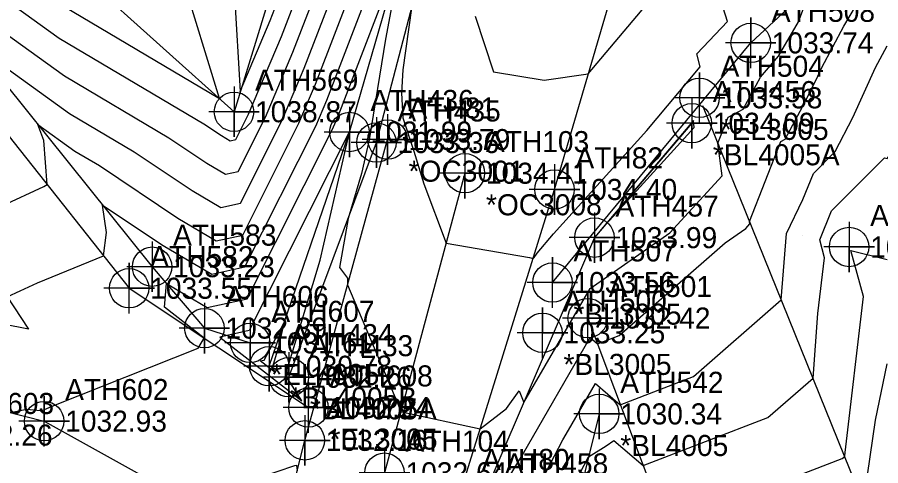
# Model space of a CAD drawing. Extents: x 1213164 to 1213550, y 766120 to 766870.
# Drawn here: x 1213316.7 to 1213419.3, y 766602.7 to 766656 of the extents above; entities that cross this region are included whole.
import ezdxf

# ---------------------------------------------------------------- set-up
doc = ezdxf.new("R2010")
doc.units = 0
for name, color, linetype in [('Default', 7, 'Continuous'), ('Exist DTM Breakline', 7, 'Continuous'), ('Exist DTM Breakline Cogo Comment', 7, 'Continuous'), ('Exist DTM Breakline Cogo Elevation', 7, 'Continuous'), ('Exist DTM Breakline Cogo Number', 7, 'Continuous'), ('Exist DTM Breakline Cogo Point CELL', 7, 'Continuous'), ('Exist DTM Crownline', 7, 'Continuous'), ('Exist DTM Crownline Cogo Comment', 7, 'Continuous'), ('Exist DTM Crownline Cogo Elevation', 7, 'Continuous'), ('Exist DTM Crownline Cogo Number', 7, 'Continuous'), ('Exist DTM Crownline Cogo Point CELL', 7, 'Continuous'), ('Exist DTM QL2 LIDAR Elevation Point', 7, 'Continuous'), ('Exist DTM Regular Point CELL', 7, 'Continuous'), ('Exist DTM Regular Point Cogo Elevation', 7, 'Continuous'), ('Exist DTM Regular Point Cogo Number', 7, 'Continuous'), ('Exist Roads EOP', 7, 'Continuous'), ('Exist Roads EOP Cogo Comment', 7, 'Continuous'), ('Exist Roads EOP Cogo Elevation', 7, 'Continuous'), ('Exist Roads EOP Cogo Number', 7, 'Continuous'), ('Exist Roads EOP Cogo Point CELL', 7, 'Continuous'), ('Exist Roads Soil', 7, 'Continuous'), ('Exist Roads Soil Cogo Comment', 7, 'Continuous'), ('Exist Roads Soil Cogo Elevation', 7, 'Continuous'), ('Exist Roads Soil Cogo Number', 7, 'Continuous'), ('Exist Roads Soil Cogo Point CELL', 7, 'Continuous')]:
    doc.layers.add(name, color=color, linetype=linetype)

msp = doc.modelspace()

# ---------------------------------------------------------------- linework, layer by layer
at = {"layer": 'Default'}
for points in [[(1213229.91, 766628.63), (1213231.61, 766625.47), (1213233.56, 766624.18), (1213260.61, 766623.01), (1213260.95, 766623.11), (1213261.75, 766623.57), (1213263.33, 766624), (1213274.44, 766627.3), (1213277.6, 766627.87), (1213300.48, 766625.1), (1213305.42, 766624.33), (1213315.52, 766622.75), (1213319.13, 766624.42), (1213326.96, 766627.62), (1213327.29, 766630.38), (1213326.85, 766633.66), (1213334.04, 766628.84), (1213339.8, 766625.45), (1213343.74, 766626.32), (1213352.15, 766643.03), (1213353.46, 766646.12), (1213362.47, 766669.52)], [(1213230, 766635.98), (1213235.84, 766637.33), (1213260.48, 766636.44), (1213263.49, 766635.93), (1213267.36, 766635.23), (1213272.93, 766634.4), (1213278.24, 766635.46), (1213299.19, 766632.93), (1213309.93, 766631.26), (1213319.85, 766635.85), (1213320.25, 766636.1), (1213319.86, 766641.32), (1213319.16, 766643.22), (1213323.53, 766640.07), (1213326.46, 766638.34), (1213335.77, 766632.11), (1213340.35, 766629.41), (1213343.48, 766630.1), (1213350.16, 766643.38), (1213352.12, 766648.01), (1213359.49, 766667.16)], [(1213229.91, 766642.9), (1213230, 766644.71), (1213234.36, 766644.36), (1213238.15, 766644.35), (1213243, 766643.74), (1213255.18, 766643.3), (1213261.95, 766642.16), (1213270.65, 766640.58), (1213274.2, 766640.05), (1213285.35, 766642.28), (1213297.9, 766640.76), (1213304.33, 766639.76), (1213310.28, 766642.51), (1213313.54, 766644.58), (1213313.3, 766647.81), (1213311.48, 766652.77), (1213322.92, 766644.54), (1213330.59, 766639.99), (1213337.5, 766635.37), (1213340.89, 766633.37), (1213343.21, 766633.88), (1213348.17, 766643.73), (1213350.78, 766649.9), (1213356.51, 766664.8)], [(1213363.53, 766657.03), (1213362.49, 766649.7), (1213362.33, 766646.97), (1213362.51, 766644.01), (1213363.81, 766640.07), (1213364.99, 766636.19), (1213367.65, 766629.14), (1213377.54, 766627.42), (1213377.97, 766627.33), (1213378.11, 766627.45), (1213378.47, 766627.94), (1213380.39, 766630.24), (1213391.47, 766642.51), (1213397.82, 766650.08), (1213397.41, 766651.62), (1213401.07, 766655.44), (1213398.13, 766664.72)], [(1213315.9, 766609.02), (1213317.84, 766609.42), (1213319.43, 766609.25), (1213319.68, 766609.27), (1213321.07, 766609.84), (1213338.2, 766616.67), (1213338.92, 766617.85), (1213334.2, 766621.55), (1213334.44, 766624.33), (1213339.26, 766621.48), (1213344.01, 766622.53), (1213354.14, 766642.68), (1213354.8, 766644.23), (1213362.46, 766664.13), (1213360.44, 766653.35), (1213358.52, 766641.4), (1213357.61, 766637.42), (1213356, 766632.06), (1213354.96, 766626.26), (1213355.91, 766624.99), (1213355.93, 766624.2), (1213361.9, 766610.07), (1213362.26, 766609.11), (1213362.55, 766609.06), (1213371.7, 766607.1), (1213374.8, 766609.52), (1213376.32, 766611.61), (1213376.87, 766610.22), (1213384.74, 766623.74), (1213394.22, 766630.34), (1213400.41, 766637.14), (1213399.92, 766641.02), (1213401.12, 766644.08), (1213402.93, 766645.05), (1213404.96, 766648.84), (1213407.13, 766651.35), (1213409.49, 766655.4), (1213411.03, 766659.6)], [(1213305.9, 766660.82), (1213322.31, 766649.01), (1213334.72, 766641.65), (1213339.22, 766638.63), (1213341.44, 766637.33), (1213342.95, 766637.66), (1213346.18, 766644.08), (1213349.44, 766651.8), (1213353.54, 766662.44)], [(1213309.95, 766661.94), (1213321.7, 766653.48), (1213338.85, 766643.3), (1213340.95, 766641.9), (1213341.98, 766641.29), (1213342.68, 766641.45), (1213344.19, 766644.44), (1213348.1, 766653.69), (1213350.56, 766660.08)], [(1213321.09, 766657.94), (1213340.71, 766646.3), (1213336.25, 766660.9)], [(1213342.51, 766658.57), (1213343.19, 766647.14), (1213346.76, 766655.58), (1213347.59, 766657.72)], [(1213371.08, 766656.07), (1213373.25, 766649.48), (1213379.3, 766648.5), (1213384.51, 766649.22), (1213392.44, 766658.66)], [(1213374.99, 766601.19), (1213376.71, 766603.99), (1213384.73, 766617.93), (1213385.6, 766617.18), (1213388.19, 766618.18), (1213400.76, 766629.17), (1213403.24, 766630.89), (1213403.72, 766631.42), (1213403.68, 766631.72), (1213407.39, 766641.2), (1213407.92, 766641.48), (1213410, 766645.38), (1213411.56, 766648.44), (1213412.27, 766650), (1213414.88, 766654.88), (1213417.13, 766658.74)], [(1213353.03, 766538.71), (1213360.06, 766554.63), (1213361.94, 766557.96), (1213368.09, 766570.88), (1213369.21, 766573.11), (1213376.08, 766587.44), (1213384.56, 766603.77), (1213386.66, 766605.05), (1213387.56, 766605.71), (1213391.04, 766602.72), (1213405.84, 766608.43), (1213411.21, 766613.12), (1213411.8, 766620.77), (1213412.59, 766627.41), (1213412.01, 766629.52), (1213413.41, 766632.98), (1213419.7, 766639.25), (1213420, 766639.17), (1213420.37, 766639.63), (1213420.63, 766640), (1213424.33, 766645.67), (1213426.37, 766650), (1213427.85, 766652.15), (1213430, 766656.29)], [(1213374.46, 766592.25), (1213381.5, 766605.8), (1213382.19, 766606.92), (1213385.38, 766612.47), (1213388.32, 766609.95), (1213397.02, 766613.3), (1213407.44, 766622.42), (1213408.05, 766630.3), (1213410, 766634.3), (1213411.26, 766637.41), (1213413.86, 766640), (1213415.93, 766644.07), (1213418.63, 766650), (1213420, 766652.57)], [(1213397.1, 766642.87), (1213397, 766643.68), (1213385.86, 766630.52), (1213397.1, 766642.87)], [(1213350.52, 766610.43), (1213348.56, 766613.44), (1213352.67, 766627.12), (1213356.16, 766642.32), (1213356.18, 766642.4), (1213356.19, 766642.48), (1213356.14, 766642.34), (1213356.13, 766642.33), (1213344.27, 766618.75), (1213341.64, 766618.17), (1213340.77, 766617.96), (1213350.52, 766610.43)], [(1213353.14, 766525.66), (1213361.52, 766549.65), (1213362.63, 766551.86), (1213367.85, 766562.26), (1213372.47, 766571.97), (1213375.15, 766577.31), (1213377.7, 766582.63), (1213380.85, 766588.68), (1213389.17, 766593.76), (1213392.72, 766596.38), (1213393.76, 766595.49), (1213414.67, 766603.56), (1213414.97, 766603.82), (1213415.01, 766604.26), (1213417.21, 766622.79), (1213415.71, 766628.28), (1213420, 766627.19)], [(1213346.03, 766615.26), (1213348.37, 766619.62), (1213347.73, 766616.82), (1213346.98, 766614.32), (1213347.34, 766613.78), (1213345.56, 766615.15), (1213346.03, 766615.26)], [(1213356.49, 766527.5), (1213362.2, 766543.86), (1213364.74, 766548.91), (1213376.71, 766572.75), (1213376.86, 766573.06), (1213377.13, 766573.6), (1213382.4, 766576.55), (1213385.24, 766579.91), (1213390, 766583.08), (1213391.68, 766584.23), (1213396.48, 766588.25), (1213409.54, 766593.3), (1213418.74, 766594.53), (1213417.67, 766601.59), (1213418.64, 766608.1), (1213420, 766614.82)], [(1213337.1, 766598.45), (1213349.69, 766602.72), (1213349.86, 766602.78), (1213349.95, 766602.12)]]:
    msp.add_lwpolyline(points, dxfattribs=at)
at = {"layer": 'Exist DTM Breakline'}
for points in [[(1213393.73, 766837.71), (1213387.94, 766804.2), (1213372.97, 766750.1), (1213364.41, 766714.77), (1213354.91, 766685.16), (1213342.45, 766644.74), (1213315.98, 766668.51), (1213286.51, 766700.01), (1213270.13, 766717.65)], [(1213346.63, 766614.52), (1213356.15, 766642.33), (1213365.89, 766675.98), (1213376.51, 766712.04), (1213387.8, 766751.44), (1213401.65, 766799.53), (1213406.48, 766827.99)], [(1213348.97, 766613.21), (1213359.36, 766641.08), (1213368.17, 766674.74), (1213379.29, 766710.8), (1213391.46, 766750.47), (1213404.9, 766798.24), (1213409.09, 766827.1)], [(1213258.22, 766718.72), (1213280.97, 766690.21), (1213305.18, 766660.62), (1213332.72, 766626.34), (1213338.93, 766619.05), (1213344.38, 766617.29)], [(1213396.81, 766643.38), (1213385.25, 766629.79), (1213372.13, 766599.17), (1213360.99, 766554.14), (1213352.93, 766525.55), (1213348.45, 766509.5)], [(1213385.82, 766608.86), (1213377.01, 766573.1), (1213363.67, 766531.44)]]:
    msp.add_lwpolyline(points, dxfattribs=at)
at = {"layer": 'Exist DTM Breakline Cogo Point CELL'}
for points in [[(1213342.45, 766647.74), (1213342.45, 766641.74), (1213342.45, 766644.74), (1213345.45, 766644.74), (1213339.45, 766644.74)], [(1213396.81, 766646.38), (1213396.81, 766640.38), (1213396.81, 766643.38), (1213399.81, 766643.38), (1213393.81, 766643.38)], [(1213356.15, 766645.33), (1213356.15, 766639.33), (1213356.15, 766642.33), (1213359.15, 766642.33), (1213353.15, 766642.33)], [(1213359.36, 766644.08), (1213359.36, 766638.08), (1213359.36, 766641.08), (1213362.36, 766641.08), (1213356.36, 766641.08)], [(1213385.25, 766632.79), (1213385.25, 766626.79), (1213385.25, 766629.79), (1213388.25, 766629.79), (1213382.25, 766629.79)], [(1213332.72, 766629.34), (1213332.72, 766623.34), (1213332.72, 766626.34), (1213335.72, 766626.34), (1213329.72, 766626.34)], [(1213338.93, 766622.05), (1213338.93, 766616.05), (1213338.93, 766619.05), (1213341.93, 766619.05), (1213335.93, 766619.05)], [(1213344.38, 766620.29), (1213344.38, 766614.29), (1213344.38, 766617.29), (1213347.38, 766617.29), (1213341.38, 766617.29)], [(1213346.63, 766617.52), (1213346.63, 766611.52), (1213346.63, 766614.52), (1213349.63, 766614.52), (1213343.63, 766614.52)], [(1213348.97, 766616.21), (1213348.97, 766610.21), (1213348.97, 766613.21), (1213351.97, 766613.21), (1213345.97, 766613.21)], [(1213385.82, 766611.86), (1213385.82, 766605.86), (1213385.82, 766608.86), (1213388.82, 766608.86), (1213382.82, 766608.86)]]:
    msp.add_lwpolyline(points, dxfattribs=at)
for centre in [(1213342.45, 766644.74), (1213396.81, 766643.38), (1213356.15, 766642.33), (1213359.36, 766641.08), (1213385.25, 766629.79), (1213332.72, 766626.34), (1213338.93, 766619.05), (1213344.38, 766617.29), (1213346.63, 766614.52), (1213348.97, 766613.21), (1213385.82, 766608.86)]:
    msp.add_circle(centre, 2.34, dxfattribs=at)
at = {"layer": 'Exist DTM Crownline'}
msp.add_lwpolyline([(1213369.87, 766637.44), (1213360.32, 766601.88), (1213348.56, 766557.41), (1213336.15, 766511.05)], dxfattribs=at)
at = {"layer": 'Exist DTM Crownline Cogo Point CELL'}
for points in [[(1213369.87, 766640.44), (1213369.87, 766634.44), (1213369.87, 766637.44), (1213372.87, 766637.44), (1213366.87, 766637.44)], [(1213360.32, 766604.88), (1213360.32, 766598.88), (1213360.32, 766601.88), (1213363.32, 766601.88), (1213357.32, 766601.88)]]:
    msp.add_lwpolyline(points, dxfattribs=at)
for centre in [(1213369.87, 766637.44), (1213360.32, 766601.88)]:
    msp.add_circle(centre, 2.34, dxfattribs=at)
at = {"layer": 'Exist DTM QL2 LIDAR Elevation Point'}
for p, q in [((1213410, 766650), (1213410, 766650)), ((1213410, 766640), (1213410, 766640)), ((1213410, 766630), (1213410, 766630))]:
    msp.add_line(p, q, dxfattribs=at)
at = {"layer": 'Exist DTM Regular Point CELL'}
msp.add_lwpolyline([(1213415.5, 766631.68), (1213415.5, 766625.68), (1213415.5, 766628.68), (1213418.5, 766628.68), (1213412.5, 766628.68)], dxfattribs=at)
msp.add_circle((1213415.5, 766628.68), 2.34, dxfattribs=at)
at = {"layer": 'Exist Roads EOP'}
for points in [[(1213344.56, 766509.06), (1213357.66, 766555.92), (1213369.4, 766599.7), (1213380.5, 766635.51), (1213390.23, 766668.75)], [(1213327.95, 766513.13), (1213339.55, 766560.47), (1213350.85, 766605.72), (1213360.68, 766641.43)]]:
    msp.add_lwpolyline(points, dxfattribs=at)
at = {"layer": 'Exist Roads EOP Cogo Point CELL'}
for points in [[(1213360.68, 766644.43), (1213360.68, 766638.43), (1213360.68, 766641.43), (1213363.68, 766641.43), (1213357.68, 766641.43)], [(1213380.5, 766638.51), (1213380.5, 766632.51), (1213380.5, 766635.51), (1213383.5, 766635.51), (1213377.5, 766635.51)], [(1213350.85, 766608.72), (1213350.85, 766602.72), (1213350.85, 766605.72), (1213353.85, 766605.72), (1213347.85, 766605.72)]]:
    msp.add_lwpolyline(points, dxfattribs=at)
for centre in [(1213360.68, 766641.43), (1213380.5, 766635.51), (1213350.85, 766605.72)]:
    msp.add_circle(centre, 2.34, dxfattribs=at)
at = {"layer": 'Exist Roads Soil'}
msp.add_line((1213426.4, 766575.59), (1213398.12, 766645.45), dxfattribs=at)
for points in [[(1213380.26, 766624.46), (1213403.81, 766652.91), (1213435.34, 766682.17), (1213462.6, 766704.33), (1213495.25, 766719.33)], [(1213255.38, 766715.7), (1213279.2, 766688.85), (1213302.65, 766658.35), (1213330, 766623.78), (1213351.29, 766609.62)], [(1213295.97, 766652.47), (1213318.05, 766618.91), (1213300.95, 766622.28), (1213264.73, 766630.95), (1213235.84, 766637.33)], [(1213233.88, 766629.04), (1213261.45, 766622.83), (1213319.9, 766608), (1213346.63, 766593.15)], [(1213384.45, 766620.24), (1213400.55, 766577.45)]]:
    msp.add_lwpolyline(points, dxfattribs=at)
at = {"layer": 'Exist Roads Soil Cogo Point CELL'}
for points in [[(1213403.81, 766649.91), (1213403.81, 766655.91), (1213403.81, 766652.91), (1213406.81, 766652.91), (1213400.81, 766652.91)], [(1213397.74, 766643.39), (1213397.74, 766649.39), (1213397.74, 766646.39), (1213400.74, 766646.39), (1213394.74, 766646.39)], [(1213330, 766620.78), (1213330, 766626.78), (1213330, 766623.78), (1213333, 766623.78), (1213327, 766623.78)], [(1213380.26, 766621.46), (1213380.26, 766627.46), (1213380.26, 766624.46), (1213383.26, 766624.46), (1213377.26, 766624.46)], [(1213384.45, 766617.24), (1213384.45, 766623.24), (1213384.45, 766620.24), (1213387.45, 766620.24), (1213381.45, 766620.24)], [(1213379.08, 766615.49), (1213379.08, 766621.49), (1213379.08, 766618.49), (1213382.08, 766618.49), (1213376.08, 766618.49)], [(1213351.29, 766606.62), (1213351.29, 766612.62), (1213351.29, 766609.62), (1213354.29, 766609.62), (1213348.29, 766609.62)], [(1213319.9, 766605), (1213319.9, 766611), (1213319.9, 766608), (1213322.9, 766608), (1213316.9, 766608)]]:
    msp.add_lwpolyline(points, dxfattribs=at)
for centre in [(1213403.81, 766652.91), (1213397.74, 766646.39), (1213380.26, 766624.46), (1213330, 766623.78), (1213384.45, 766620.24), (1213379.08, 766618.49), (1213351.29, 766609.62), (1213319.9, 766608)]:
    msp.add_circle(centre, 2.34, dxfattribs=at)

# ---------------------------------------------------------------- texts
at = {"layer": 'Exist DTM Breakline Cogo Comment'}
for s, p in [('*BL4005A', (1213399.31, 766638.38)), ('*EL4005', (1213346.88, 766612.29)), ('*BL4005B', (1213349.13, 766609.52)), ('*BL4005A', (1213351.47, 766608.21)), ('*BL4005', (1213388.32, 766603.86))]:
    msp.add_text(s, height=2.5, dxfattribs=at).set_placement(p)
at = {"layer": 'Exist DTM Breakline Cogo Elevation'}
for s, p in [('1038.87', (1213344.95, 766643.49)), ('1034.09', (1213399.31, 766642.12)), ('1031.99', (1213358.65, 766641.08)), ('1033.36', (1213361.86, 766639.83)), ('1033.99', (1213387.75, 766628.54)), ('1033.23', (1213335.22, 766625.09)), ('1032.39', (1213341.43, 766617.8)), ('1031.61', (1213346.88, 766616.04)), ('1030.78', (1213349.13, 766613.27)), ('1032.26', (1213351.47, 766611.96)), ('1030.34', (1213388.32, 766607.61)), ('1032.26', (1213308.82, 766605.1))]:
    msp.add_text(s, height=2.5, dxfattribs=at).set_placement(p)
at = {"layer": 'Exist DTM Breakline Cogo Number'}
for s, p in [('ATH569', (1213344.95, 766647.24)), ('ATH456', (1213399.31, 766645.88)), ('ATH436', (1213358.65, 766644.83)), ('ATH435', (1213361.86, 766643.58)), ('ATH457', (1213387.75, 766632.29)), ('ATH583', (1213335.22, 766628.84)), ('ATH606', (1213341.43, 766621.55)), ('ATH607', (1213346.88, 766619.79)), ('ATH434', (1213349.13, 766617.02)), ('ATH433', (1213351.47, 766615.71)), ('ATH542', (1213388.32, 766611.36)), ('ATH603', (1213308.82, 766608.85)), ('ATH458', (1213374.63, 766601.67))]:
    msp.add_text(s, height=2.5, dxfattribs=at).set_placement(p)
at = {"layer": 'Exist DTM Crownline Cogo Comment'}
msp.add_text('*OC3008', height=2.5, dxfattribs=at).set_placement((1213372.37, 766632.44))
at = {"layer": 'Exist DTM Crownline Cogo Elevation'}
for s, p in [('1034.41', (1213372.37, 766636.19)), ('1032.64', (1213362.82, 766600.62))]:
    msp.add_text(s, height=2.5, dxfattribs=at).set_placement(p)
at = {"layer": 'Exist DTM Crownline Cogo Number'}
for s, p in [('ATH103', (1213372.37, 766639.94)), ('ATH104', (1213362.82, 766604.38))]:
    msp.add_text(s, height=2.5, dxfattribs=at).set_placement(p)
at = {"layer": 'Exist DTM Regular Point Cogo Elevation'}
msp.add_text('1029.03', height=2.5, dxfattribs=at).set_placement((1213418, 766627.43))
at = {"layer": 'Exist DTM Regular Point Cogo Number'}
msp.add_text('ATH535', height=2.5, dxfattribs=at).set_placement((1213418, 766631.18))
at = {"layer": 'Exist Roads EOP Cogo Comment'}
msp.add_text('*OC3001', height=2.5, dxfattribs=at).set_placement((1213363.18, 766636.43))
at = {"layer": 'Exist Roads EOP Cogo Elevation'}
for s, p in [('1033.79', (1213363.18, 766640.18)), ('1034.40', (1213383, 766634.26)), ('1032.16', (1213353.35, 766604.47))]:
    msp.add_text(s, height=2.5, dxfattribs=at).set_placement(p)
at = {"layer": 'Exist Roads EOP Cogo Number'}
for s, p in [('ATH81', (1213363.18, 766643.93)), ('ATH82', (1213383, 766638.01)), ('ATH79', (1213353.35, 766608.22)), ('ATH80', (1213371.9, 766602.2))]:
    msp.add_text(s, height=2.5, dxfattribs=at).set_placement(p)
at = {"layer": 'Exist Roads Soil Cogo Comment'}
for s, p in [('*EL3005', (1213400.24, 766641.39)), ('*BL3005', (1213382.76, 766619.46)), ('*BL3005', (1213381.58, 766613.49)), ('*EL3005', (1213353.79, 766604.62))]:
    msp.add_text(s, height=2.5, dxfattribs=at).set_placement(p)
at = {"layer": 'Exist Roads Soil Cogo Elevation'}
for s, p in [('1033.74', (1213406.31, 766651.66)), ('1033.58', (1213400.24, 766645.14)), ('1033.56', (1213382.76, 766623.21)), ('1033.55', (1213332.5, 766622.53)), ('1032.42', (1213386.95, 766618.99)), ('1033.25', (1213381.58, 766617.24)), ('1032.24', (1213353.79, 766608.38)), ('1032.93', (1213322.4, 766606.75))]:
    msp.add_text(s, height=2.5, dxfattribs=at).set_placement(p)
at = {"layer": 'Exist Roads Soil Cogo Number'}
for s, p in [('ATH508', (1213406.31, 766655.41)), ('ATH504', (1213400.24, 766648.89)), ('ATH582', (1213332.5, 766626.28)), ('ATH507', (1213382.76, 766626.96)), ('ATH501', (1213386.95, 766622.74)), ('ATH500', (1213381.58, 766620.99)), ('ATH608', (1213353.79, 766612.12)), ('ATH602', (1213322.4, 766610.5))]:
    msp.add_text(s, height=2.5, dxfattribs=at).set_placement(p)

doc.saveas('drawing.dxf')
